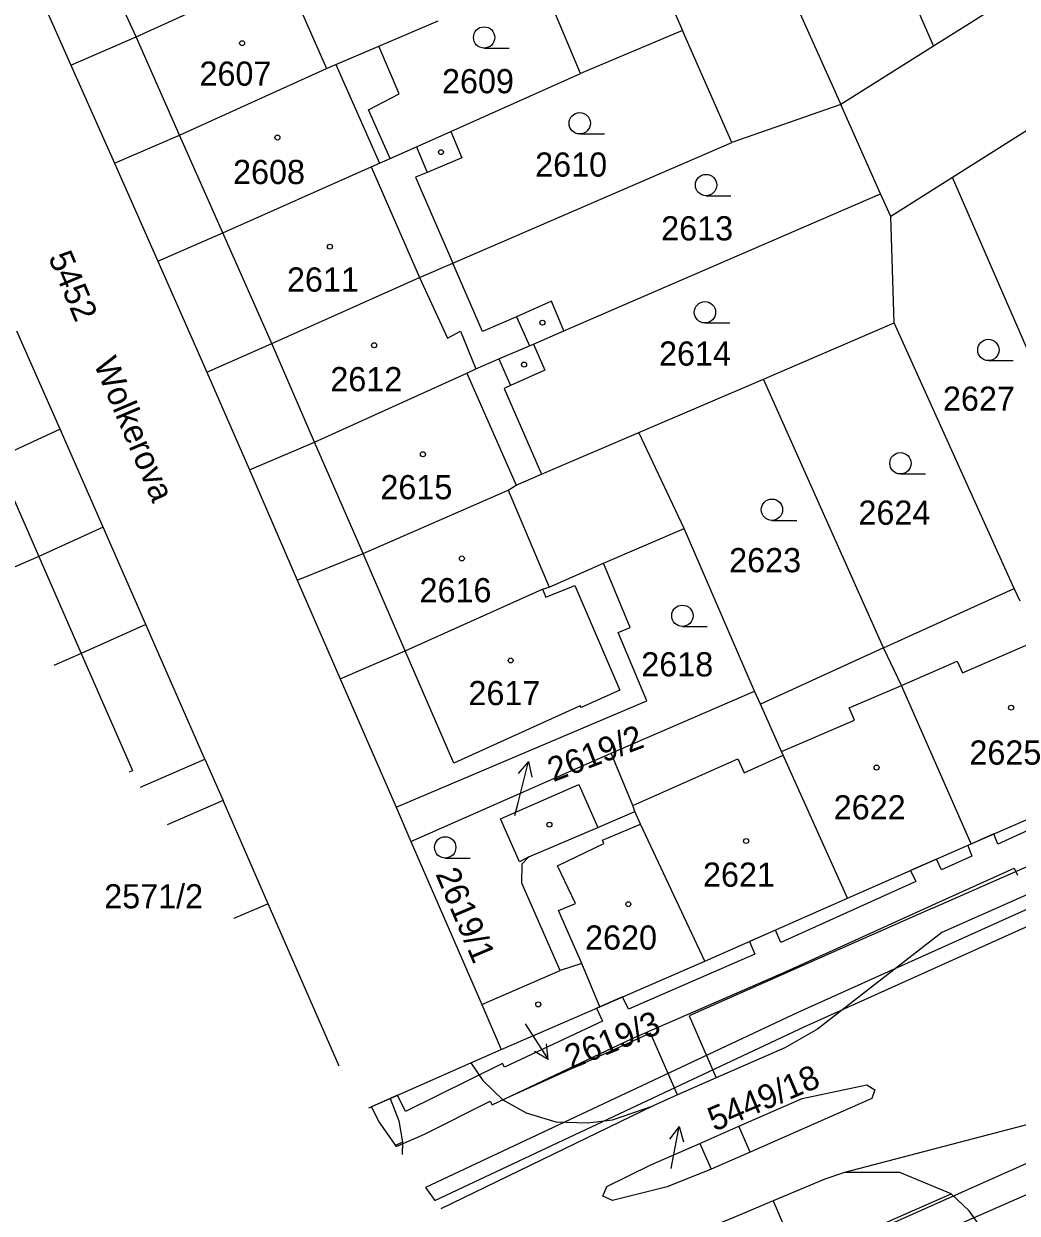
# Model space of a CAD drawing. Extents: x -821458 to -820266, y -1071458 to -1069826.
# Drawn here: x -820763.7 to -820693.8, y -1071365.5 to -1071281.9 of the extents above; entities that cross this region are included whole.
import ezdxf

# ---------------------------------------------------------------- set-up
doc = ezdxf.new("R2010")
doc.units = 0
for name, color, linetype in [('Vrstva 1', 7, 'Continuous'), ('Vrstva 13', 7, 'Continuous'), ('Vrstva 2', 7, 'Continuous'), ('Vrstva 3', 7, 'Continuous'), ('Vrstva 4', 7, 'Continuous'), ('Vrstva 5', 7, 'Continuous'), ('Vrstva 7', 7, 'Continuous')]:
    doc.layers.add(name, color=color, linetype=linetype)

msp = doc.modelspace()

# ---------------------------------------------------------------- linework, layer by layer
at = {"layer": 'Vrstva 1'}
for p, q in [((-820715.43, -1071267.03), (-820706.24, -1071287.59)), ((-820767.46, -1071268.84), (-820760.37, -1071284.81)), ((-820682.81, -1071272.87), (-820699.73, -1071283.48)), ((-820703.38, -1071275.13), (-820699.73, -1071283.48)), ((-820724.55, -1071285.39), (-820727.37, -1071278.63)), ((-820738.71, -1071283.48), (-820734.54, -1071281.69)), ((-820760.37, -1071284.81), (-820755.79, -1071282.82)), ((-820717.36, -1071282.38), (-820724.55, -1071285.39)), ((-820713.9, -1071290.24), (-820717.36, -1071282.38)), ((-820699.73, -1071283.48), (-820706.24, -1071287.59)), ((-820760.37, -1071284.81), (-820757.31, -1071291.71)), ((-820733.66, -1071289.48), (-820724.55, -1071285.39)), ((-820706.24, -1071287.59), (-820713.9, -1071290.24)), ((-820703.44, -1071293.85), (-820706.24, -1071287.59)), ((-820691.87, -1071288.59), (-820698.38, -1071292.7)), ((-820733.51, -1071298.72), (-820713.9, -1071290.24)), ((-820757.31, -1071291.71), (-820754.26, -1071298.59)), ((-820698.38, -1071292.7), (-820702.73, -1071295.45)), ((-820686.75, -1071319.48), (-820698.38, -1071292.7)), ((-820725.71, -1071303.48), (-820703.44, -1071293.85)), ((-820702.73, -1071295.45), (-820703.44, -1071293.85)), ((-820702.49, -1071302.92), (-820702.73, -1071295.45)), ((-820754.26, -1071298.59), (-820750.8, -1071306.39)), ((-820711.68, -1071306.87), (-820702.49, -1071302.92)), ((-820694.04, -1071321.59), (-820702.49, -1071302.92)), ((-820761.12, -1071310.4), (-820764.16, -1071303.5)), ((-820727.84, -1071304.41), (-820725.71, -1071303.48)), ((-820750.8, -1071306.39), (-820747.82, -1071313.25)), ((-820720.44, -1071310.62), (-820711.68, -1071306.87)), ((-820703.23, -1071325.77), (-820711.68, -1071306.87)), ((-820758.1, -1071317.28), (-820761.12, -1071310.4)), ((-820727.28, -1071313.55), (-820720.44, -1071310.62)), ((-820717.26, -1071317.38), (-820720.44, -1071310.62)), ((-820747.82, -1071313.25), (-820744.45, -1071321.01)), ((-820755.09, -1071324.13), (-820758.1, -1071317.28)), ((-820722.93, -1071319.81), (-820717.26, -1071317.38)), ((-820712.31, -1071328.8), (-820717.26, -1071317.38)), ((-820744.45, -1071321.01), (-820741.43, -1071327.94)), ((-820703.23, -1071325.77), (-820694.04, -1071321.59)), ((-820693.63, -1071322.49), (-820694.04, -1071321.59)), ((-820750.94, -1071333.58), (-820755.09, -1071324.13)), ((-820703.23, -1071325.77), (-820711.89, -1071329.72)), ((-820741.43, -1071327.94), (-820737.51, -1071336.97)), ((-820722.38, -1071333.16), (-820712.31, -1071328.8)), ((-820711.89, -1071329.72), (-820712.31, -1071328.8)), ((-820750.94, -1071333.58), (-820749.66, -1071336.49)), ((-820736.46, -1071339.38), (-820722.38, -1071333.16)), ((-820697.07, -1071339.54), (-820687.88, -1071335.5)), ((-820749.66, -1071336.49), (-820753.606, -1071338.189)), ((-820746.49, -1071343.75), (-820749.66, -1071336.49)), ((-820737.51, -1071336.97), (-820736.46, -1071339.38)), ((-820723.33, -1071338.38), (-820720.71, -1071337.26)), ((-820728.18, -1071340.45), (-820723.33, -1071338.38)), ((-820736.46, -1071339.38), (-820731.48, -1071350.82)), ((-820705.77, -1071343.36), (-820697.07, -1071339.54)), ((-820741.515, -1071355.155), (-820746.49, -1071343.75)), ((-820715.79, -1071347.79), (-820705.77, -1071343.36)), ((-820723.18, -1071350.98), (-820715.79, -1071347.79)), ((-820731.48, -1071350.82), (-820725.97, -1071348.44)), ((-820731.48, -1071350.82), (-820730.11, -1071353.98)), ((-820730.11, -1071353.98), (-820723.18, -1071350.98))]:
    msp.add_line(p, q, dxfattribs=at)
for points in [[(-820755.79, -1071282.82), (-820759.64, -1071274.41), (-820749.39, -1071269.91), (-820749.47, -1071269.73), (-820746.4, -1071268.42), (-820742.6, -1071276.89)], [(-820722.76, -1071270.2), (-820722.18, -1071271.42), (-820721.32, -1071273.37), (-820717.36, -1071282.38)], [(-820755.79, -1071282.82), (-820745.86, -1071278.3), (-820744.49, -1071277.7), (-820742.6, -1071276.89)], [(-820757.31, -1071291.71), (-820752.73, -1071289.74), (-820742.39, -1071285.05), (-820741.75, -1071284.76), (-820738.71, -1071283.48)], [(-820737.91, -1071291.37), (-820739.45, -1071287.95), (-820737.29, -1071286.84), (-820738.71, -1071283.48)], [(-820737.91, -1071291.37), (-820736.08, -1071290.55), (-820733.66, -1071289.48)], [(-820733.66, -1071289.48), (-820732.88, -1071291.32), (-820735.32, -1071292.35), (-820736.13, -1071292.69), (-820733.51, -1071298.72)], [(-820754.26, -1071298.59), (-820749.69, -1071296.59), (-820739.25, -1071291.96), (-820738.66, -1071291.7), (-820737.91, -1071291.37)], [(-820750.8, -1071306.39), (-820746.25, -1071304.37), (-820735.87, -1071299.74), (-820733.51, -1071298.72)], [(-820725.71, -1071303.48), (-820726.58, -1071301.41), (-820729.05, -1071302.49), (-820731.42, -1071303.52), (-820733.51, -1071298.72)], [(-820747.82, -1071313.25), (-820743.23, -1071311.31), (-820732.54, -1071306.45), (-820731.89, -1071306.16), (-820730.27, -1071305.46), (-820728.13, -1071304.54), (-820727.84, -1071304.41)], [(-820727.84, -1071304.41), (-820727.04, -1071306.24), (-820729.45, -1071307.33), (-820729.91, -1071307.54), (-820727.28, -1071313.55)], [(-820761.12, -1071310.4), (-820765.64, -1071312.47), (-820770.478, -1071314.514)], [(-820744.45, -1071321.01), (-820739.83, -1071319.14), (-820729.62, -1071314.67), (-820729.07, -1071314.32), (-820727.28, -1071313.55)], [(-820636.97, -1071316.64), (-820637.36, -1071317.08), (-820639.2, -1071319.35), (-820642.33, -1071322.43), (-820644.69, -1071324.22), (-820646.94, -1071325.71), (-820650.04, -1071327.31), (-820653.86, -1071329.02), (-820657.08, -1071330.4), (-820661.97, -1071331.85), (-820670.38, -1071333.7), (-820675.08, -1071335.1), (-820699.14, -1071345.77), (-820707.87, -1071352.56), (-820710.18, -1071353.88), (-820714.99, -1071355.97), (-820717.71, -1071357.17), (-820719.42, -1071357.95), (-820734.359, -1071365.197)], [(-820758.1, -1071317.28), (-820762.63, -1071319.34), (-820766.007, -1071320.787)], [(-820741.43, -1071327.94), (-820736.86, -1071325.98), (-820727.22, -1071321.65), (-820726.74, -1071321.49), (-820722.93, -1071319.81)], [(-820737.51, -1071336.97), (-820719.88, -1071329.48), (-820721.88, -1071324.68), (-820721.05, -1071324.33), (-820722.93, -1071319.81)], [(-820755.09, -1071324.13), (-820759.64, -1071326.17), (-820761.575, -1071327.007)], [(-820697.07, -1071339.54), (-820701.96, -1071328.4), (-820703.23, -1071325.77)], [(-820705.77, -1071343.36), (-820710.28, -1071333.31), (-820710.4, -1071333.04), (-820711.89, -1071329.72)], [(-820755.48, -1071335.559), (-820750.94, -1071333.58)], [(-820720.71, -1071337.26), (-820720.86, -1071336.84), (-820722.38, -1071333.16)], [(-820728.18, -1071340.45), (-820728.82, -1071340.8), (-820730.16, -1071337.77), (-820724.66, -1071335.36), (-820723.33, -1071338.38)], [(-820629.87, -1071337.4), (-820630.92, -1071336.63), (-820633.66, -1071335.41), (-820636.65, -1071334.85), (-820639.5, -1071334.97), (-820642.22, -1071335.6), (-820646.76, -1071337.17), (-820651.91, -1071339.71), (-820660.24, -1071345.49), (-820688.88, -1071358.16), (-820705.99, -1071362.63), (-820707.35, -1071363.11), (-820711, -1071364.62), (-820713.77, -1071365.79), (-820719.56, -1071368.14), (-820729.538, -1071371.963)], [(-820715.79, -1071347.79), (-820720.32, -1071338.16), (-820720.71, -1071337.26)], [(-820725.97, -1071348.44), (-820728.66, -1071342.3), (-820728.65, -1071340.93), (-820728.18, -1071340.45)], [(-820746.49, -1071343.75), (-820748.903, -1071344.788)], [(-820723.18, -1071350.98), (-820724.44, -1071347.94), (-820725.97, -1071348.44)], [(-820739.417, -1071358.099), (-820737.92, -1071357.44), (-820732.26, -1071354.93), (-820730.11, -1071353.98)], [(-820718.45, -1071363.63), (-820722.3, -1071364.6), (-820722.96, -1071364.29), (-820722.68, -1071363.62), (-820719.6, -1071362.09), (-820716.16, -1071360.59), (-820713.41, -1071359.38), (-820708.96, -1071357.43), (-820704.4, -1071356.48), (-820703.85, -1071356.82), (-820704.05, -1071357.44), (-820712.6, -1071361.2), (-820715.35, -1071362.39), (-820718.45, -1071363.63)]]:
    msp.add_lwpolyline(points, dxfattribs=at)
at = {"layer": 'Vrstva 13'}
for p, q in [((-820738.719, -1071359.079), (-820737.492, -1071360.801)), ((-820735.43, -1071363.695), (-820734.781, -1071364.606))]:
    msp.add_line(p, q, dxfattribs=at)
for points in [[(-820734.781, -1071364.606), (-820708.81, -1071352.39), (-820645.59, -1071323.94), (-820641.98, -1071309.26), (-820642.81, -1071308.03), (-820646.53, -1071323.16), (-820709.27, -1071351.39), (-820735.43, -1071363.695)], [(-820626.97, -1071332.11), (-820650.32, -1071343.25), (-820661.25, -1071348.1), (-820672.22, -1071352.93), (-820683.3, -1071357.67), (-820690.24, -1071360.69), (-820705.28, -1071367.39), (-820716.31, -1071372.14), (-820726.26, -1071376.562)], [(-820725.073, -1071378.228), (-820715.51, -1071373.98), (-820693.48, -1071364.32), (-820690.23, -1071362.88), (-820689.78, -1071363.88), (-820687.95, -1071363.08), (-820688.4, -1071362.07), (-820682.5, -1071359.51), (-820671.42, -1071354.77), (-820660.45, -1071349.93), (-820649.48, -1071345.07), (-820628.03, -1071334.83)], [(-820693.08, -1071338.6), (-820695.2, -1071339.57), (-820695.48, -1071338.84), (-820697.31, -1071339.65), (-820697.03, -1071340.4), (-820699.15, -1071341.36), (-820699.51, -1071340.61), (-820701.34, -1071341.41), (-820700.97, -1071342.18), (-820710.45, -1071346.47), (-820710.83, -1071345.6), (-820712.66, -1071346.41), (-820712.28, -1071347.28), (-820721.17, -1071351.16), (-820721.58, -1071350.29), (-820723.18, -1071350.98), (-820723.41, -1071351.08), (-820722.99, -1071351.99), (-820729.88, -1071355.24), (-820730.02, -1071354.97), (-820736.85, -1071358.34), (-820737.4, -1071357.2), (-820737.92, -1071357.44), (-820739.23, -1071358.01), (-820738.719, -1071359.079)], [(-820737.492, -1071360.801), (-820736.31, -1071360.28), (-820735.5, -1071359.93), (-820730.88, -1071357.63), (-820730.76, -1071357.87), (-820720.95, -1071353.25), (-820710.08, -1071348.5), (-820699.09, -1071343.52), (-820694.05, -1071341.24), (-820693.82, -1071341.73)]]:
    msp.add_lwpolyline(points, dxfattribs=at)
at = {"layer": 'Vrstva 3'}
for p, q in [((-820731.313, -1071283.62), (-820729.563, -1071283.62)), ((-820724.593, -1071289.65), (-820722.843, -1071289.65)), ((-820715.713, -1071293.99), (-820713.963, -1071293.99)), ((-820715.793, -1071302.93), (-820714.043, -1071302.93)), ((-820695.863, -1071305.58), (-820694.113, -1071305.58)), ((-820702.043, -1071313.54), (-820700.293, -1071313.54)), ((-820711.083, -1071316.81), (-820709.333, -1071316.81)), ((-820717.373, -1071324.26), (-820715.623, -1071324.26)), ((-820734.053, -1071340.54), (-820732.303, -1071340.54))]:
    msp.add_line(p, q, dxfattribs=at)
for centre in [(-820731.313, -1071282.87), (-820724.593, -1071288.9), (-820715.713, -1071293.24), (-820715.793, -1071302.18), (-820695.863, -1071304.83), (-820702.043, -1071312.79), (-820711.083, -1071316.06), (-820717.373, -1071323.51), (-820734.053, -1071339.79)]:
    msp.add_circle(centre, 0.75, dxfattribs=at)
at = {"layer": 'Vrstva 4'}
for p, q in [((-820744.32, -1071280.7), (-820742.39, -1071285.05)), ((-820752.73, -1071289.74), (-820755.79, -1071282.82)), ((-820741.75, -1071284.76), (-820738.66, -1071291.7)), ((-820749.69, -1071296.59), (-820752.73, -1071289.74)), ((-820736.08, -1071290.55), (-820735.32, -1071292.35)), ((-820739.25, -1071291.96), (-820735.87, -1071299.74)), ((-820746.25, -1071304.37), (-820749.69, -1071296.59)), ((-820735.87, -1071299.74), (-820733.9, -1071304.01)), ((-820729.05, -1071302.49), (-820728.13, -1071304.54)), ((-820733.9, -1071304.01), (-820732.98, -1071303.51)), ((-820732.98, -1071303.51), (-820731.89, -1071306.16)), ((-820743.23, -1071311.31), (-820746.25, -1071304.37)), ((-820730.27, -1071305.46), (-820729.45, -1071307.33)), ((-820732.54, -1071306.45), (-820729.07, -1071314.32)), ((-820739.83, -1071319.14), (-820743.23, -1071311.31)), ((-820765.64, -1071312.47), (-820762.63, -1071319.34)), ((-820729.62, -1071314.67), (-820726.74, -1071321.49)), ((-820762.63, -1071319.34), (-820759.64, -1071326.17)), ((-820736.86, -1071325.98), (-820739.83, -1071319.14)), ((-820726.97, -1071322.2), (-820724.93, -1071321.38)), ((-820724.93, -1071321.38), (-820721.78, -1071328.73)), ((-820727.22, -1071321.65), (-820726.97, -1071322.2)), ((-820697.68, -1071327.52), (-820692.39, -1071325.23)), ((-820759.64, -1071326.17), (-820756.04, -1071334.39)), ((-820733.44, -1071333.86), (-820736.86, -1071325.98)), ((-820701.96, -1071328.4), (-820698.06, -1071326.7)), ((-820699.79, -1071344.05), (-820660.58, -1071326.76)), ((-820698.06, -1071326.7), (-820697.68, -1071327.52)), ((-820721.78, -1071328.73), (-820724.5, -1071329.96)), ((-820705.64, -1071329.97), (-820701.96, -1071328.4)), ((-820724.56, -1071329.83), (-820733.44, -1071333.86)), ((-820724.5, -1071329.96), (-820724.56, -1071329.83)), ((-820705.27, -1071330.85), (-820705.64, -1071329.97)), ((-820710.4, -1071333.04), (-820705.27, -1071330.85)), ((-820720.86, -1071336.84), (-820713.47, -1071333.57)), ((-820713.47, -1071333.57), (-820713.04, -1071334.55)), ((-820713.04, -1071334.55), (-820710.28, -1071333.31)), ((-820756.249, -1071334.481), (-820756.04, -1071334.39)), ((-820722.99, -1071339.27), (-820720.32, -1071338.16)), ((-820726.15, -1071341.09), (-820722.89, -1071339.52)), ((-820722.89, -1071339.52), (-820722.99, -1071339.27)), ((-820724.88, -1071343.73), (-820726.15, -1071341.09)), ((-820726.09, -1071344.23), (-820724.88, -1071343.73)), ((-820724.44, -1071347.94), (-820726.09, -1071344.23)), ((-820712.6, -1071361.2), (-820713.41, -1071359.38)), ((-820716.16, -1071360.59), (-820715.35, -1071362.39))]:
    msp.add_line(p, q, dxfattribs=at)
for points in [[(-820699.79, -1071344.05), (-820716.91, -1071351.63), (-820714.99, -1071355.97)], [(-820717.71, -1071357.17), (-820719.62, -1071352.83), (-820730.01, -1071357.52)], [(-820732.26, -1071354.93), (-820731.4, -1071356.17), (-820730.01, -1071357.52)], [(-820737.92, -1071357.44), (-820737.31, -1071359), (-820737.05, -1071360.5)], [(-820730.01, -1071357.52), (-820728.37, -1071358.44), (-820726.27, -1071359.07), (-820724.02, -1071359.14), (-820722.3, -1071358.92), (-820719.42, -1071357.95)], [(-820737.549, -1071360.721), (-820737.05, -1071360.5)], [(-820737.05, -1071360.5), (-820737.082, -1071361.376)], [(-820698.47, -1071364.14), (-820702.08, -1071362.63), (-820705.99, -1071362.63)], [(-820711, -1071364.62), (-820709.18, -1071368.85), (-820698.47, -1071364.14)], [(-820696.22, -1071366.7), (-820697.22, -1071365.32), (-820698.47, -1071364.14)]]:
    msp.add_lwpolyline(points, dxfattribs=at)
at = {"layer": 'Vrstva 5'}
for centre in [(-820748.327, -1071283.269), (-820745.847, -1071289.899), (-820734.347, -1071290.929), (-820742.157, -1071297.569), (-820727.217, -1071302.909), (-820739.047, -1071304.499), (-820728.507, -1071305.859), (-820735.617, -1071312.159), (-820732.877, -1071319.479), (-820729.447, -1071326.649), (-820694.267, -1071329.969), (-820703.727, -1071334.179), (-820726.727, -1071338.189), (-820712.897, -1071339.339), (-820721.177, -1071343.779), (-820727.507, -1071350.819)]:
    msp.add_circle(centre, 0.175, dxfattribs=at)
at = {"layer": 'Vrstva 7'}
for p, q in [((-820728.204, -1071333.748), (-820728.932, -1071334.599)), ((-820728.93, -1071336.66), (-820728.204, -1071333.748)), ((-820728.204, -1071333.748), (-820727.96, -1071334.841)), ((-820729.16, -1071337.55), (-820728.93, -1071336.66)), ((-820728.44, -1071352.18), (-820726.806, -1071354.697)), ((-820726.806, -1071354.697), (-820726.931, -1071353.584)), ((-820726.806, -1071354.697), (-820727.771, -1071354.13)), ((-820717.597, -1071359.394), (-820718.28, -1071360.282)), ((-820718.17, -1071362.34), (-820717.597, -1071359.394)), ((-820717.597, -1071359.394), (-820717.297, -1071360.473))]:
    msp.add_line(p, q, dxfattribs=at)

# ---------------------------------------------------------------- texts
at = {"layer": 'Vrstva 2'}
for s, p in [('2607', (-820751.327, -1071286.259)), ('2609', (-820734.277, -1071286.79)), ('2610', (-820727.727, -1071292.65)), ('2608', (-820748.967, -1071293.17)), ('2613', (-820718.867, -1071297.13)), ('2611', (-820745.177, -1071300.729)), ('2614', (-820719.017, -1071305.93)), ('2612', (-820742.127, -1071307.729)), ('2627', (-820699.057, -1071309.1)), ('2615', (-820738.607, -1071315.32)), ('2624', (-820704.997, -1071317.11)), ('2623', (-820714.087, -1071320.45)), ('2616', (-820735.857, -1071322.56)), ('2618', (-820720.267, -1071327.769)), ('2617', (-820732.417, -1071329.79)), ('2625', (-820697.197, -1071333.97)), ('2622', (-820706.737, -1071337.82)), ('2621', (-820715.927, -1071342.55)), ('2571/2', (-820758.025, -1071344.07)), ('2620', (-820724.217, -1071346.97))]:
    msp.add_text(s, height=1.7, dxfattribs=at).set_placement(p)
for s, rotation, p in [('5452', 293, (-820761.982, -1071298.314)), ('2619/2', 21, (-820726.445, -1071335.203)), ('2619/1', 293, (-820734.754, -1071341.649)), ('2619/3', 22, (-820725.218, -1071355.397)), ('5449/18', 23, (-820715.13, -1071359.772))]:
    msp.add_text(s, height=1.7, rotation=rotation, dxfattribs=at).set_placement(p)
at = {"layer": 'Vrstva 7'}
msp.add_text('Wolkerova', height=1.7, rotation=293, dxfattribs=at).set_placement((-820758.796, -1071305.772))

doc.saveas('drawing.dxf')
